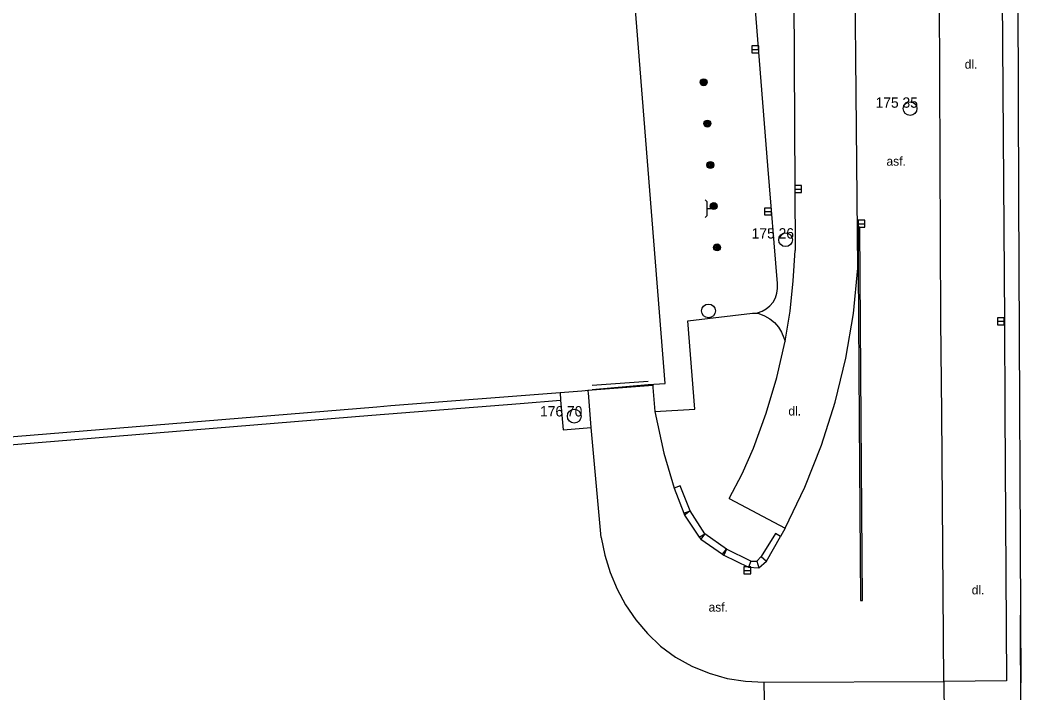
# Model space of a CAD drawing. Extents: x -541281 to -539153, y -1183881 to -1182141.
# Drawn here: x -539516.2 to -539443.7, y -1183345.7 to -1183296.9 of the extents above; entities that cross this region are included whole.
import ezdxf

# ---------------------------------------------------------------- set-up
doc = ezdxf.new("R2010")
doc.units = 0
for name, color, linetype in [('Vrstva 10', 7, 'Continuous'), ('Vrstva 11', 7, 'Continuous'), ('Vrstva 25', 7, 'Continuous'), ('Vrstva 27', 7, 'Continuous'), ('Vrstva 4', 7, 'Continuous'), ('Vrstva 40', 7, 'Continuous'), ('Vrstva 5', 7, 'Continuous'), ('Vrstva 6', 7, 'Continuous'), ('Vrstva 7', 7, 'Continuous')]:
    doc.layers.add(name, color=color, linetype=linetype)

msp = doc.modelspace()

# ---------------------------------------------------------------- linework, layer by layer
at = {"layer": 'Vrstva 10'}
for p, q in [((-539460.18, -1183289.41), (-539460.05, -1183313.65)), ((-539449.49, -1183318.7), (-539449.6, -1183294.43)), ((-539445.06, -1183294.49), (-539444.88, -1183318.73)), ((-539449.41, -1183325.43), (-539449.49, -1183318.7)), ((-539444.88, -1183318.73), (-539444.86, -1183325.29)), ((-539449.28, -1183344.9), (-539449.41, -1183325.43)), ((-539444.86, -1183325.29), (-539444.73, -1183344.84)), ((-539474.1, -1183334.45), (-539474.84, -1183326.48)), ((-539468.81, -1183330.87), (-539468.11, -1183332.7)), ((-539468.11, -1183332.7), (-539468.06, -1183332.83)), ((-539468.06, -1183332.83), (-539467, -1183334.44)), ((-539467, -1183334.44), (-539466.89, -1183334.57)), ((-539466.89, -1183334.57), (-539465.32, -1183335.67)), ((-539462.13, -1183336.16), (-539461.11, -1183334.38)), ((-539465.32, -1183335.67), (-539465.22, -1183335.73)), ((-539465.22, -1183335.73), (-539463.44, -1183336.61)), ((-539462.69, -1183336.66), (-539462.13, -1183336.16)), ((-539463.44, -1183336.61), (-539462.69, -1183336.66)), ((-539462.23, -1183349.5), (-539462.29, -1183344.93)), ((-539444.73, -1183344.84), (-539449.28, -1183344.9)), ((-539449.28, -1183344.9), (-539449.24, -1183349.43))]:
    msp.add_line(p, q, dxfattribs=at)
for points in [[(-539455.5, -1183314.94), (-539455.819, -1183281.842), (-539455.82, -1183281.69)], [(-539460.77, -1183320.22), (-539460.421, -1183318.043), (-539460.181, -1183315.851), (-539460.05, -1183313.65)], [(-539457.143, -1183324.635), (-539456.368, -1183321.444), (-539455.82, -1183318.207), (-539455.5, -1183314.94)], [(-539463.06, -1183327.98), (-539462.143, -1183325.44), (-539461.379, -1183322.851), (-539460.77, -1183320.22)], [(-539474.84, -1183326.48), (-539475.03, -1183323.96), (-539475.07, -1183323.78), (-539470.37, -1183323.4), (-539470.36, -1183323.58), (-539470.22, -1183325.31)], [(-539460.78, -1183333.77), (-539459.354, -1183330.813), (-539458.14, -1183327.763), (-539457.143, -1183324.635)], [(-539470.22, -1183325.31), (-539469.57, -1183328.35), (-539468.81, -1183330.87)], [(-539464.82, -1183331.63), (-539463.884, -1183329.832), (-539463.06, -1183327.98)], [(-539464.82, -1183331.63), (-539460.78, -1183333.77), (-539461.11, -1183334.38)], [(-539474.1, -1183334.45), (-539473.848, -1183335.733), (-539473.468, -1183336.984), (-539472.962, -1183338.189), (-539472.336, -1183339.337), (-539471.597, -1183340.416), (-539470.752, -1183341.413), (-539469.81, -1183342.32)], [(-539469.81, -1183342.32), (-539468.715, -1183343.117), (-539467.534, -1183343.779), (-539466.284, -1183344.298), (-539464.98, -1183344.666), (-539463.643, -1183344.877), (-539462.29, -1183344.93)]]:
    msp.add_lwpolyline(points, dxfattribs=at)
at = {"layer": 'Vrstva 11'}
for p, q in [((-539462.02, -1183307.49), (-539463.22, -1183292.54)), ((-539461.34, -1183316.05), (-539462.02, -1183307.49)), ((-539455.27, -1183325.98), (-539455.37, -1183311.96)), ((-539455.48, -1183314.96), (-539455.41, -1183325.98)), ((-539467.31, -1183325.14), (-539467.82, -1183318.75)), ((-539477.09, -1183323.95), (-539477.05, -1183324.49)), ((-539490.74, -1183325.59), (-539479.99, -1183324.74)), ((-539479.99, -1183324.74), (-539477.05, -1183324.49)), ((-539523.68, -1183328.27), (-539490.74, -1183325.59)), ((-539470.22, -1183325.31), (-539467.31, -1183325.14)), ((-539455.41, -1183325.98), (-539455.31, -1183339.02)), ((-539455.17, -1183339.02), (-539455.27, -1183325.98)), ((-539468.11, -1183332.7), (-539467.67, -1183332.53)), ((-539467.67, -1183332.53), (-539468.06, -1183332.83)), ((-539466.59, -1183334.18), (-539467.67, -1183332.53)), ((-539467, -1183334.44), (-539466.59, -1183334.18)), ((-539466.59, -1183334.18), (-539466.89, -1183334.57)), ((-539465.03, -1183335.31), (-539466.59, -1183334.18)), ((-539465.32, -1183335.67), (-539465.03, -1183335.31)), ((-539465.03, -1183335.31), (-539465.22, -1183335.73)), ((-539463.25, -1183336.18), (-539465.03, -1183335.31)), ((-539463.25, -1183336.18), (-539463.44, -1183336.61)), ((-539463.25, -1183336.18), (-539462.82, -1183336.18)), ((-539462.51, -1183335.84), (-539462.82, -1183336.18)), ((-539462.82, -1183336.18), (-539462.69, -1183336.66)), ((-539462.51, -1183335.84), (-539462.13, -1183336.16)), ((-539455.31, -1183339.02), (-539455.17, -1183339.02)), ((-539462.29, -1183344.93), (-539449.28, -1183344.9))]:
    msp.add_line(p, q, dxfattribs=at)
for points in [[(-539455.37, -1183311.96), (-539455.46, -1183311.95), (-539455.48, -1183314.96)], [(-539463.13, -1183318.2), (-539462.783, -1183318.155), (-539462.45, -1183318.046), (-539462.143, -1183317.877), (-539461.873, -1183317.655), (-539461.648, -1183317.385), (-539461.478, -1183317.079), (-539461.368, -1183316.747), (-539461.321, -1183316.4), (-539461.34, -1183316.05)], [(-539467.82, -1183318.75), (-539463.13, -1183318.2), (-539462.68, -1183318.22)], [(-539462.68, -1183318.22), (-539462.271, -1183318.377), (-539461.892, -1183318.598), (-539461.554, -1183318.876), (-539461.264, -1183319.205), (-539461.031, -1183319.576), (-539460.86, -1183319.98), (-539460.77, -1183320.22)], [(-539477.05, -1183324.49), (-539476.86, -1183326.64), (-539474.84, -1183326.48)], [(-539467.67, -1183332.53), (-539468.39, -1183330.7), (-539468.81, -1183330.87)], [(-539461.11, -1183334.38), (-539461.48, -1183334.17), (-539462.51, -1183335.84)]]:
    msp.add_lwpolyline(points, dxfattribs=at)
at = {"layer": 'Vrstva 25'}
for centre, radius in [((-539466.68, -1183301.45), 0.25), ((-539466.68, -1183301.45), 0.2), ((-539466.68, -1183301.45), 0.15), ((-539466.68, -1183301.45), 0.1), ((-539466.68, -1183301.45), 0.05), ((-539466.41, -1183304.45), 0.25), ((-539466.41, -1183304.45), 0.2), ((-539466.41, -1183304.45), 0.15), ((-539466.41, -1183304.45), 0.1), ((-539466.41, -1183304.45), 0.05), ((-539466.19, -1183307.45), 0.25), ((-539466.19, -1183307.45), 0.2), ((-539466.19, -1183307.45), 0.15), ((-539466.19, -1183307.45), 0.1), ((-539466.19, -1183307.45), 0.05), ((-539465.95, -1183310.43), 0.25), ((-539465.95, -1183310.43), 0.2), ((-539465.95, -1183310.43), 0.15), ((-539465.95, -1183310.43), 0.1), ((-539465.95, -1183310.43), 0.05), ((-539465.71, -1183313.42), 0.25), ((-539465.71, -1183313.42), 0.2), ((-539465.71, -1183313.42), 0.15), ((-539465.71, -1183313.42), 0.1), ((-539465.71, -1183313.42), 0.05)]:
    msp.add_circle(centre, radius, dxfattribs=at)
at = {"layer": 'Vrstva 27'}
for p, q in [((-539463.19, -1183299.07), (-539462.69, -1183299.07)), ((-539460.08, -1183309.19), (-539459.58, -1183309.19)), ((-539466.56, -1183309.968), (-539466.418, -1183310.11)), ((-539466.418, -1183311.11), (-539466.418, -1183310.11)), ((-539466.418, -1183310.61), (-539465.93, -1183310.61)), ((-539462.27, -1183310.82), (-539461.77, -1183310.82)), ((-539466.56, -1183311.25), (-539466.418, -1183311.11)), ((-539455.49, -1183311.71), (-539454.99, -1183311.71)), ((-539445.39, -1183318.78), (-539444.89, -1183318.78)), ((-539463.76, -1183336.84), (-539463.26, -1183336.84))]:
    msp.add_line(p, q, dxfattribs=at)
for points in [[(-539463.19, -1183299.32), (-539462.69, -1183299.32), (-539462.69, -1183298.82), (-539463.19, -1183298.82)], [(-539460.08, -1183309.44), (-539459.58, -1183309.44), (-539459.58, -1183308.94), (-539460.08, -1183308.94)], [(-539462.27, -1183311.07), (-539461.77, -1183311.07), (-539461.77, -1183310.57), (-539462.27, -1183310.57)], [(-539455.49, -1183311.96), (-539454.99, -1183311.96), (-539454.99, -1183311.46), (-539455.49, -1183311.46)], [(-539445.39, -1183319.03), (-539444.89, -1183319.03), (-539444.89, -1183318.53), (-539445.39, -1183318.53)], [(-539463.76, -1183337.09), (-539463.26, -1183337.09), (-539463.26, -1183336.59), (-539463.76, -1183336.59)]]:
    msp.add_lwpolyline(points, close=True, dxfattribs=at)
for centre in [(-539451.72, -1183303.36), (-539460.74, -1183312.87), (-539466.33, -1183318.03), (-539476.06, -1183325.66)]:
    msp.add_circle(centre, 0.5, dxfattribs=at)
at = {"layer": 'Vrstva 5'}
for p, q in [((-539469.47, -1183323.3), (-539471.76, -1183294.4)), ((-539475.51, -1183323.82), (-539470.71, -1183323.37)), ((-539470.71, -1183323.37), (-539469.47, -1183323.3)), ((-539489.35, -1183324.89), (-539477.09, -1183323.95)), ((-539477.09, -1183323.95), (-539475.51, -1183323.82)), ((-539549.12, -1183329.76), (-539490.38, -1183324.99))]:
    msp.add_line(p, q, dxfattribs=at)
at = {"layer": 'Vrstva 6'}
for p, q in [((-539474.76, -1183323.41), (-539470.71, -1183323.12)), ((-539474.76, -1183323.72), (-539470.71, -1183323.37)), ((-539490.38, -1183324.99), (-539489.35, -1183324.89))]:
    msp.add_line(p, q, dxfattribs=at)
at = {"layer": 'Vrstva 7'}
for p, q in [((-539443.92, -1183294.84), (-539443.86, -1183309.76)), ((-539443.86, -1183309.76), (-539443.69, -1183345)), ((-539443.74, -1183340.09), (-539443.68, -1183355.53))]:
    msp.add_line(p, q, dxfattribs=at)

# ---------------------------------------------------------------- texts
at = {"layer": 'Vrstva 4'}
for s, p in [('175 35 ', (-539454.22, -1183303.3)), ('175 26 ', (-539463.2, -1183312.78)), ('176 70 ', (-539478.54, -1183325.68))]:
    msp.add_text(s, height=0.75, dxfattribs=at).set_placement(p)
at = {"layer": 'Vrstva 40'}
for s, p in [('dl.', (-539447.76, -1183300.469)), ('asf.', (-539453.428, -1183307.501)), ('dl.', (-539460.54, -1183325.609)), ('dl.', (-539447.251, -1183338.577)), ('asf.', (-539466.324, -1183339.826))]:
    msp.add_text(s, height=0.65, dxfattribs=at).set_placement(p)

doc.saveas('drawing.dxf')
